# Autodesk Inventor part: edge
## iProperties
Shininess: 64.0
Length Units: 11269
Angle Units: 11279
Time Units: 11290
Mass Units: 11283
Length Display Precision: 3
Angle Display Precision: 2
Compacted: True
Part Number: edge
Document SubType Name: Modeling
Created: 2004-10
Material: Standard
Designer: W. Holzwarth
Manufacturer: Standard
Standards Organization: Custom
Density: 0.0
Volumn: 0.0
Area: 0.0
PropertySet Name: Model Information
Control State: 0
Master: False
Checked Out: False
Author: W. Holzwarth
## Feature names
1. Basis1
